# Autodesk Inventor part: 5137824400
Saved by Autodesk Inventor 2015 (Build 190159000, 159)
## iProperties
Created: 2020-07
Part Number: 5137824400
Checked By: TraceParts S.A.
Material: Generic
Catalog Web Link: www.traceparts.com
Document SubType Name: Modeling
Designer: TraceParts
Density: 1 g/cm^3
Appearance: Default
Company: TraceParts S.A.
Author: TraceParts
REFERENCE: 5137824400
DESIGN: CVAT/4-16000/630 N D PTC 3KW (230/400V) 50HZ - 5137824400
SUPPLIER: Soler & Palau
TraceParts.PartNumber: 10-14122018-105188
TraceParts.PartTitle: CVAT-N
TraceParts.InstanceId: 10-14122018-105188EN8ULU0S3AI21RSMVY03FE8VJ
TraceParts.PartStatus: Published
TraceParts.PartVersion: 1.0.4
TRACEPARTS: TRACEPARTS
TraceParts.PartLanguage: en
TraceParts.ClassPath: SOLER_PALAU:10-14122018-105188
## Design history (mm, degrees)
feature "5137824400"
body "Solid1"
